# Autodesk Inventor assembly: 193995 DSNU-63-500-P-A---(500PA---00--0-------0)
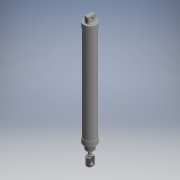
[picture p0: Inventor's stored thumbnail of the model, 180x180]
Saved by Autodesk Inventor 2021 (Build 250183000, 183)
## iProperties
Part Number: 193995 DSNU-63-500-P-A---(500PA---00--0-------0)
Catalog Web Link: www.cadenas.de
Description: DSNU (m)-Round cylinder, Modular system
Vendor: FESTO
Document SubType Name: Assembly
Designer: partserver
Manufacturer: FESTO
Mass: 719.326 g
Surface Area: 3103.34 cm^2
Volume: 719.326 cm^3
Density: 1 g/cm^3
Category: PARTsolutions
Company: FESTO
PSOL_IDENT_0: {ATYP=ASSISTANT},{DATA=script=$CADENAS_DATA/23d-libs/festo/webfesto.vbb/&M_FAMILY=DSNU&M_GROUP=01&M_
PSOL_IDENT_1: PARTNO=193995&IDCODE1=DSNU-63-500-P-A&IDCODE2=&C_DSNU_DM=63&C_DSNU_HEAD=DSNU&HUB=500&M_AA=A&M_DAA=P&
PSOL_IDENT_2: S_SMS=N&VCSD_UPDATE_YYIDENT11=DSNU-63-500-P-A&customer_number_cns=&MATES=1&LOD=HI&LOCKERP=1}
NB: 193995 DSNU-63-500-P-A---(500PA---00--0-------0)
NN: DSNU (m)
NT: Round cylinder, Modular system
NBSYN: $TNR. $IDCODE1.---($HUB.$DA.$PE.$ZD.$VS.$KA.$K2A.$K6.$K3.$K5.$K8.$KP.$R3.$R8.$TB.$KS.$LS.$ATEX.$HUBST.)
LINA: 193995 DSNU-63-500-P-A
CATALOG: Festo
OFFICIAL_STANDARD_NUMBERS: ISO 6432
TNR: 193995
TYP: DSNU-63
KDM: 63
HUB: 500
HUBST: 0
DA: P
PE: A
ZD: -
VS: -
KA: -
K2A: 0
K6: 0
K3: -
K5: -
K8: 0
KP: -
R3: -
R8: -
TB: -
KS: -
LS: -
ATEX: -
A1: 70
A2: 500
A3: 10
A4: 87.5
AB: 44
AM: 32
B: 45
BB: 4
BE: M45x1,5
BS: 11
B1: 72
B2: 17
B3: 44
B4: 15
B5: 36
B6: 18
B7: 4
CD: 16
D: 70
D1: 45
D2: 20
D3: 65.4
D4: 16
D5: 66
D6: 60
D7: 45
EE: G3/8
EW: 21
F: 52
FF: M8
F1: 36
H: 72
H1: 8
KK: M16x1.5
K1: M10
K2: 3.5
KV: 0
KW: 10
KV2: 24
KW2: 8
L: 16
LH: 15
LK: 28
L1: 672.2
L2: 594.2
L3: 13
L4: 33
L5: 30
L6: 77
L7: 44
L8: 28
L9: 32
L10: 117.2
L11: 132.2
L12: 94.2
L13: 184.2
ST: 11
SW: 17
T: 16
WH: 45
X: 4.7
XC: 656.2
SUPPLIER: FESTO
ARTICLENO: 193995 DSNU-63-500-P-A---(500PA---00--0-------0)
BOMINFO: 193995 DSNU-63-500-P-A
CREATOR: CADENAS GmbH
Title: 193995 DSNU-63-500-P-A
Author: Cadenas PARTsolutions
Comments: Round cylinder, Modular system
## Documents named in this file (5)
- C:\Users\mahra\Documents\Undervisning\2020-interactive-mech-systems\training-device\193995 DSNU-63-500-P-A---(500PA---00--0-------0).iam
- C:\Users\mahra\Documents\Undervisning\2020-interactive-mech-systems\training-device\193995 DSNU-63-500-P---(A----0-ZR).ipt
- C:\Users\mahra\Documents\Undervisning\2020-interactive-mech-systems\training-device\193995 DSNU-63-500-P---(A---00--0-KS).ipt
- C:\Users\mahra\Documents\Undervisning\2020-interactive-mech-systems\training-device\DIN-439-B - M16x1_5(F).ipt
- C:\Users\mahra\Documents\Undervisning\2020-interactive-mech-systems\training-device\IMS-01-002.ipt
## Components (4 placed, 4 different names)
1. 193995 DSNU-63-500-P---(A----0-ZR):1 — ZR_XY@1 <-> KS_XY@3, ZR_Z@1 <-> KS_Z@3, ZR_YZ@1 <-> KS_YZ@3, Angle:3
2. 193995 DSNU-63-500-P---(A---00--0-KS):1 — ZR_XY@1 <-> KS_XY@3, ZR_Z@1 <-> KS_Z@3, ZR_YZ@1 <-> KS_YZ@3, NUT1_XY@3 <-> 2CYL_XY@4, NUT1_Z@3 <-> 2CYL_Z@4, NUT1_YZ@3 <-> 2CYL_YZ@4, Mate:5
3. DIN-439-B - M16x1_5(F):1 — NUT1_XY@3 <-> 2CYL_XY@4, NUT1_Z@3 <-> 2CYL_Z@4, NUT1_YZ@3 <-> 2CYL_YZ@4, Mate:6
4. IMS-01-002:1 — Mate:5, Mate:6, Angle:3
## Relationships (9: Mate 6, Angle 3)
- ZR_XY@1 <-> KS_XY@3 [Mate]: 193995 DSNU-63-500-P---(A----0-ZR):1 ↔ 193995 DSNU-63-500-P---(A---00--0-KS):1
- ZR_Z@1 <-> KS_Z@3 [Mate]: 193995 DSNU-63-500-P---(A----0-ZR):1 ↔ 193995 DSNU-63-500-P---(A---00--0-KS):1
- ZR_YZ@1 <-> KS_YZ@3 [Angle]: 193995 DSNU-63-500-P---(A----0-ZR):1 ↔ 193995 DSNU-63-500-P---(A---00--0-KS):1
- NUT1_XY@3 <-> 2CYL_XY@4 [Mate]: 193995 DSNU-63-500-P---(A---00--0-KS):1 ↔ DIN-439-B - M16x1_5(F):1
- NUT1_Z@3 <-> 2CYL_Z@4 [Mate]: 193995 DSNU-63-500-P---(A---00--0-KS):1 ↔ DIN-439-B - M16x1_5(F):1
- NUT1_YZ@3 <-> 2CYL_YZ@4 [Angle]: 193995 DSNU-63-500-P---(A---00--0-KS):1 ↔ DIN-439-B - M16x1_5(F):1
- Mate:5: 193995 DSNU-63-500-P---(A---00--0-KS):1 ↔ IMS-01-002:1
- Mate:6: DIN-439-B - M16x1_5(F):1 ↔ IMS-01-002:1
- Angle:3: 193995 DSNU-63-500-P---(A----0-ZR):1 ↔ IMS-01-002:1
